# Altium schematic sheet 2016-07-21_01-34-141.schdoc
size 679 x 287 mm; SheetNumber: 1; SheetTotal: 1
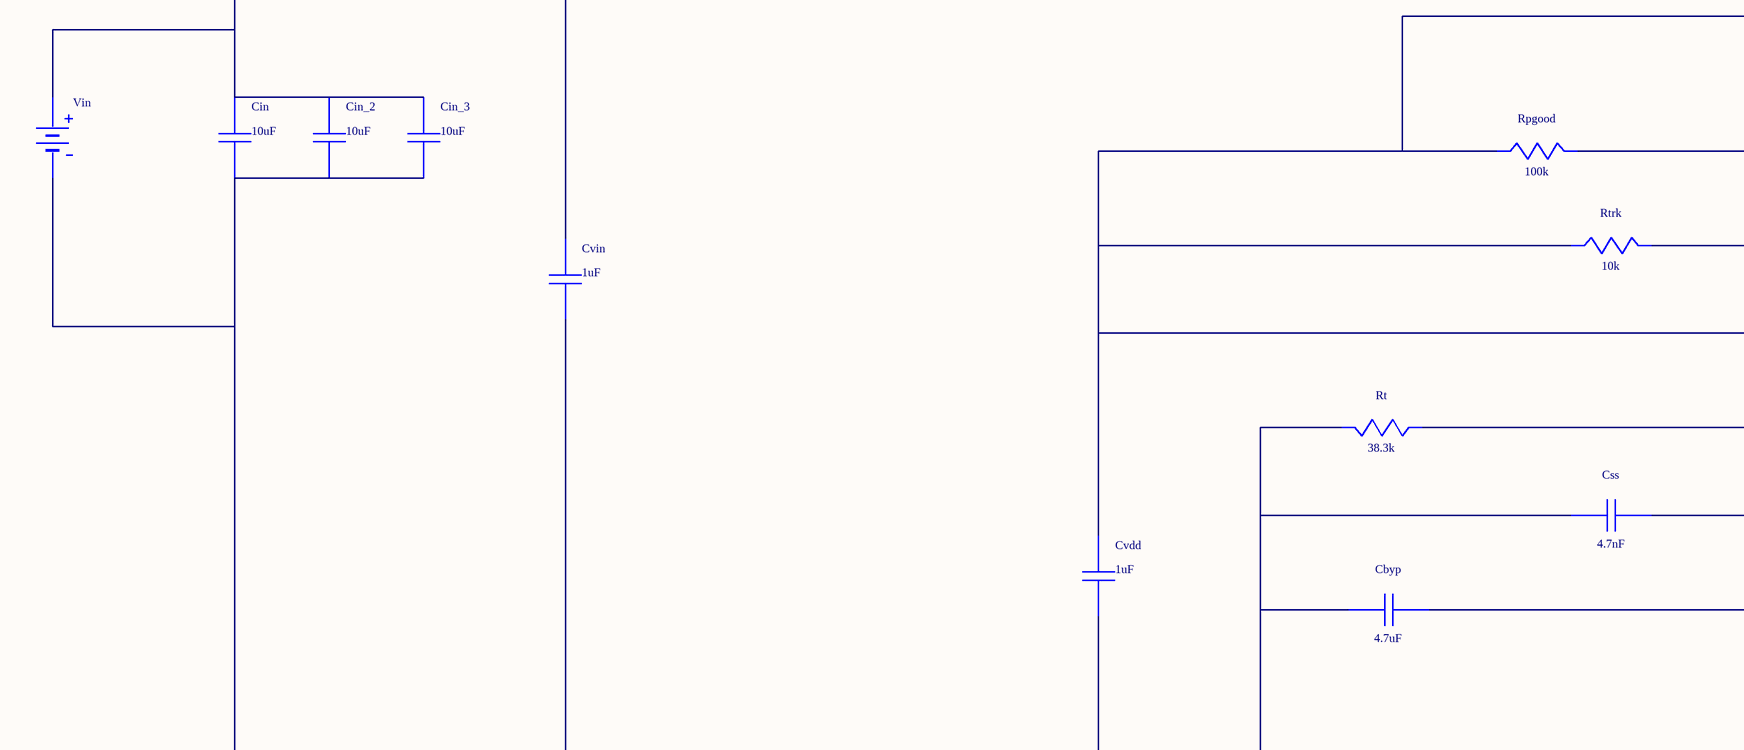
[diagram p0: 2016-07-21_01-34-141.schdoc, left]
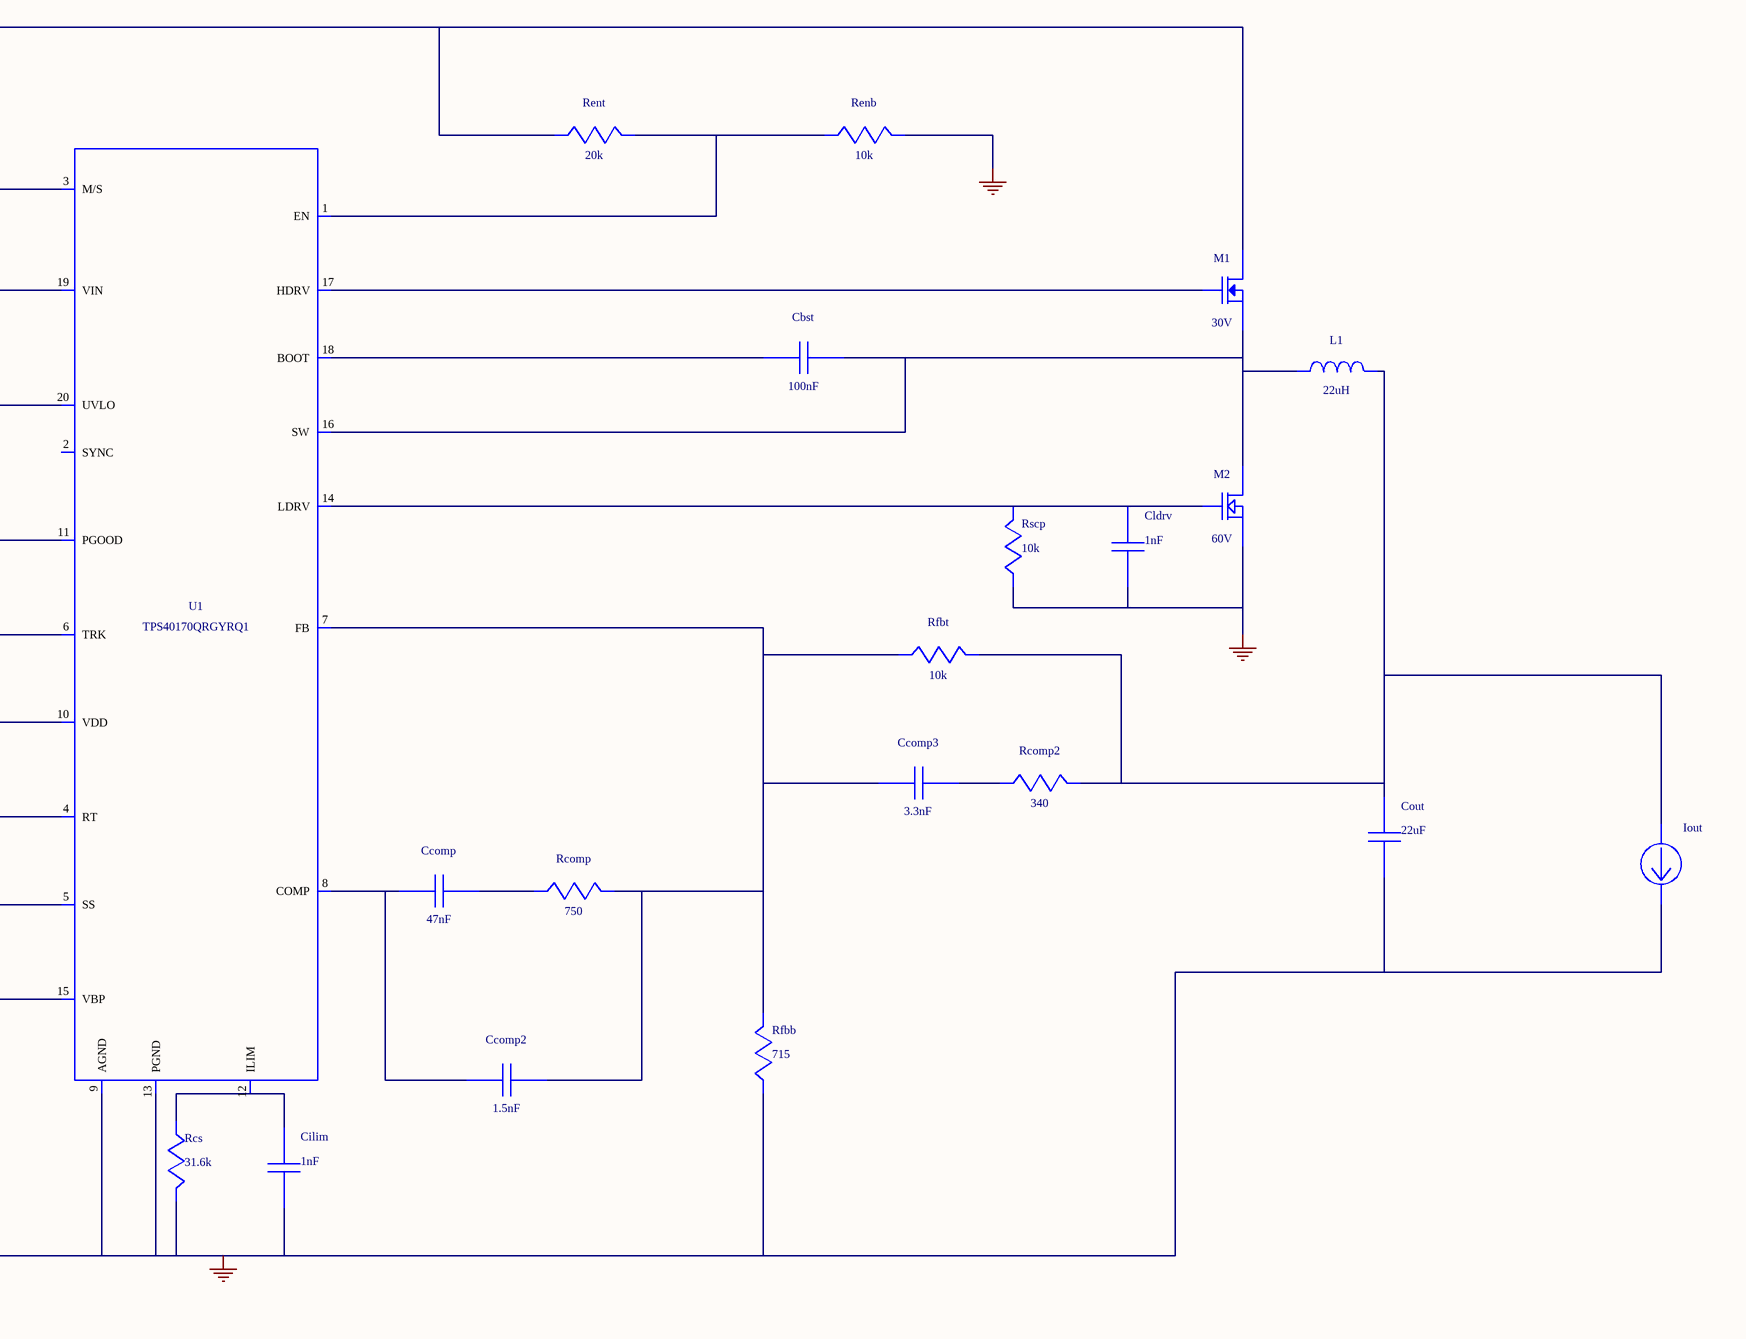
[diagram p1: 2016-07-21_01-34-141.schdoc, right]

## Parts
Cbst  value 100nF  (hidden comment: C0805C104K5RACTU)
Cbyp  value 4.7uF  (hidden comment: GRM21BR61E475KA12L)
Ccomp  value 47nF  (hidden comment: TMK212B7473KD-T)
Ccomp2  value 1.5nF  (hidden comment: CC0805KRX7R9BB152)
Ccomp3  value 3.3nF  (hidden comment: GRM216R71E332KA01D)
Cilim  value 1nF  (hidden comment: GRM216R71E102KA01D)
Cin  value 10uF  (hidden comment: GRM32ER7YA106KA12L)
Cin_2  value 10uF  (hidden comment: GRM32ER7YA106KA12L)
Cin_3  value 10uF  (hidden comment: GRM32ER7YA106KA12L)
Cldrv  value 1nF  (hidden comment: GRM033R71C102KA01D)
Cout  value 22uF  (hidden comment: GRM31CR61A226KE19L)
Css  value 4.7nF  (hidden comment: GRM033R70J472KA01D)
Cvdd  value 1uF  (hidden comment: GRM188R61C105KA93D)
Cvin  value 1uF  (hidden comment: C3216X5R1H105K)
Iout  WB_CURRENT_LOAD  (value not drawn)
L1  value 22uH  (hidden comment: SER2915H-223KL)
M1  value 30V  (hidden comment: CSD17309Q3)
M2  value 60V  (hidden comment: CSD18532Q5B)
Rcomp  value 750  (hidden comment: CRCW0402750RFKED)
Rcomp2  value 340  (hidden comment: CRCW0402340RFKED)
Rcs  value 31.6k  (hidden comment: CRCW040231K6FKED)
Renb  value 10k  (hidden comment: CRCW040210K0FKED)
Rent  value 20k  (hidden comment: CRCW040220K0FKED)
Rfbb  value 715  (hidden comment: CRCW0402715RFKED)
Rfbt  value 10k  (hidden comment: CRCW040210K0FKED)
Rpgood  value 100k  (hidden comment: CRCW0402100KFKED)
Rscp  value 10k  (hidden comment: CRCW040210K0FKED)
Rt  value 38.3k  (hidden comment: CRCW040238K3FKED)
Rtrk  value 10k  (hidden comment: CRCW040210K0FKED)
U1  TPS40170QRGYRQ1
Vin  WB_BATTERY  (value not drawn)

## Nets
0: Cbyp.2 Cilim.1 Cin.2 Cin_2.2 Cin_3.2 Cldrv.2 Cout.2 Css.2 Cvdd.2 Cvin.2 Iout.2(-) M2.1(Source) M2.2(Source) M2.3(Source) Rcs.1 Renb.1 Rfbb.2 Rscp.2 Rt.1 U1.9(AGND) U1.13(PGND) U1.21(ETPAD) Vin.2(-)
NetCbst_1: Cbst.1 U1.18(BOOT)
NetCbst_2: Cbst.2 L1.1 M1.1(Source) M1.2(Source) M1.3(Source) M2.5(Drain) M2.6(Drain) M2.7(Drain) M2.8(Drain) M2.9(Drain) U1.16(SW)
NetCbyp_1: Cbyp.1 U1.15(VBP)
NetCcomp2_1: Ccomp2.1 Ccomp3.2 Rcomp.1 Rfbb.1 Rfbt.2 U1.7(FB)
NetCcomp3_1: Ccomp3.1 Rcomp2.2
NetCcomp_1: Ccomp.1 Rcomp.2
NetCcomp_2: Ccomp.2 Ccomp2.2 U1.8(COMP)
NetCilim_2: Cilim.2 Rcs.2 U1.12(ILIM)
NetCin_1: Cin.1 Cin_2.1 Cin_3.1 Cvin.1 M1.5(Drain) M1.6(Drain) M1.7(Drain) M1.8(Drain) M1.9(Drain) Rent.2 U1.3(M/S) U1.19(VIN) Vin.1(+)
NetCldrv_1: Cldrv.1 M2.4(Gate) Rscp.1 U1.14(LDRV)
NetCout_1: Cout.1 Iout.1(+) L1.2 Rcomp2.1 Rfbt.1
NetCss_1: Css.1 U1.5(SS)
NetCvdd_1: Cvdd.1 Rpgood.2 Rtrk.2 U1.10(VDD) U1.20(UVLO)
NetM1_4: M1.4(Gate) U1.17(HDRV)
NetRenb_2: Renb.2 Rent.1 U1.1(EN)
NetRpgood_1: Rpgood.1 U1.11(PGOOD)
NetRt_2: Rt.2 U1.4(RT)
NetRtrk_1: Rtrk.1 U1.6(TRK)

Not connected (* = marked no-connect by the designer): U1 2(SYNC)

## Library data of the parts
Cbst = C0805C104K5RACTU: Manufacturer Name: Kemet
Cbyp = GRM21BR61E475KA12L: GRM21BR61E475KA1; Manufacturer Name: MuRata
Ccomp = TMK212B7473KD-T: Manufacturer Name: Taiyo Yuden
Ccomp2 = CC0805KRX7R9BB152: CC0805KRX7R9BB15; Manufacturer Name: Yageo America
Ccomp3 = GRM216R71E332KA01D: GRM216R71E332KA0; Manufacturer Name: MuRata
Cilim = GRM216R71E102KA01D: GRM216R71E102KA0; Manufacturer Name: MuRata
Cin Cin_2 Cin_3 = GRM32ER7YA106KA12L: GRM32ER7YA106KA1; Manufacturer Name: MuRata
Cldrv = GRM033R71C102KA01D: GRM033R71C102KA0; Manufacturer Name: MuRata
Cout = GRM31CR61A226KE19L: GRM31CR61A226KE1; Manufacturer Name: MuRata
Css = GRM033R70J472KA01D: GRM033R70J472KA0; Manufacturer Name: MuRata
Cvdd = GRM188R61C105KA93D: GRM188R61C105KA9; Manufacturer Name: MuRata
Cvin = C3216X5R1H105K: Manufacturer Name: TDK
L1 = SER2915H-223KL: Manufacturer Name: Coilcraft
M1 = CSD17309Q3: Manufacturer Name: Texas Instruments
M2 = CSD18532Q5B: Manufacturer Name: Texas Instruments
Rcomp = CRCW0402750RFKED: Manufacturer Name: Vishay-Dale
Rcomp2 = CRCW0402340RFKED: Manufacturer Name: Vishay-Dale
Rcs = CRCW040231K6FKED: Manufacturer Name: Vishay-Dale
Renb Rfbt Rscp Rtrk = CRCW040210K0FKED: Manufacturer Name: Vishay-Dale
Rent = CRCW040220K0FKED: Manufacturer Name: Vishay-Dale
Rfbb = CRCW0402715RFKED: Manufacturer Name: Vishay-Dale
Rpgood = CRCW0402100KFKED: Manufacturer Name: Vishay-Dale
Rt = CRCW040238K3FKED: Manufacturer Name: Vishay-Dale
U1 = TPS40170QRGYRQ1: Manufacturer Name: Texas Instruments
